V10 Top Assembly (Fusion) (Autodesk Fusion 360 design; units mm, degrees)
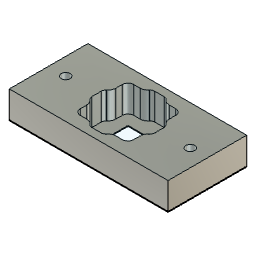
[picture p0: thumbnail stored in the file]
sketch "Sketch1" plane through (0, 0, 0) normal (0, 0, 1) x axis (1, 0, 0)
  line L1 (17.82, 5.59) -> (0, 5.59)
  line L2 (17.82, 8.82) -> (17.82, 0)
  line L3 (9.8201, 1.0463) -> (9.8489, 1.0851)
  line L4 (6.544, 1.41) -> (7.2771, 1.41)
  line L5 (10.5429, 7.41) -> (11.276, 7.41)
  line L6 (12.2349, 3.4711) -> (12.2737, 3.4999)
  line L7 (1.92, 4.41) -> (15.9, 4.41)
  line L8 (0, 3.621) -> (17.82, 3.621)
  line L9 (12.2737, 5.3201) -> (12.2349, 5.3489)
  line L10 (10.09, 0) -> (10.09, 8.82)
  line L11 (11.276, 1.41) -> (10.5429, 1.41)
  line L12 (9.699, 8.82) -> (9.699, 0)
  line L13 (5.5851, 5.3489) -> (5.5463, 5.3201)
  line L14 (12.437, 4.9474) -> (12.437, 3.8726)
  line L15 (17.82, 4.41) -> (15.9, 4.41)
  line L16 (15.9, 8.82) -> (15.9, 4.41)
  line L17 (5.5463, 3.4999) -> (5.5851, 3.4711)
  line L18 (17.82, 0) -> (0, 0)
  line L19 (17.82, 5.199) -> (0, 5.199)
  line L20 (17.82, 3.23) -> (0, 3.23)
  line L21 (0, 0) -> (0, 8.82)
  line L22 (11.91, 2.7771) -> (11.91, 2.044)
  line L23 (1.92, 4.41) -> (0, 4.41)
  line L24 (8.3726, 0.883) -> (9.4474, 0.883)
  line L25 (5.91, 2.7771) -> (5.91, 2.044)
  line L26 (1.92, 0) -> (1.92, 4.41)
  line L27 (15.9, 0) -> (15.9, 4.41)
  line L28 (9.4474, 7.937) -> (8.3726, 7.937)
  line L29 (5.383, 3.8726) -> (5.383, 4.9474)
  line L30 (9.8489, 7.7349) -> (9.8201, 7.7737)
  line L31 (5.91, 6.0429) -> (5.91, 6.776)
  line L32 (7.2771, 7.41) -> (6.544, 7.41)
  line L33 (7.9999, 7.7737) -> (7.9711, 7.7349)
  line L34 (8.121, 0) -> (8.121, 8.82)
  line L35 (1.92, 8.82) -> (1.92, 4.41)
  line L36 (7.9999, 1.0463) -> (7.9711, 1.0851)
  line L37 (11.91, 6.0429) -> (11.91, 6.776)
  line L38 (0, 8.82) -> (17.82, 8.82)
  line L39 (7.73, 8.82) -> (7.73, 0)
  arc A1 centre (12.81, 6.0429) radius 0.9 clockwise from (12.2737, 5.3201) to (11.91, 6.0429)
  arc A2 centre (11.937, 3.8726) radius 0.5 clockwise from (12.437, 3.8726) to (12.2349, 3.4711)
  arc A3 centre (9.4474, 1.383) radius 0.5 clockwise from (9.8489, 1.0851) to (9.4474, 0.883)
  arc A4 centre (11.276, 6.776) radius 0.634 clockwise from (11.276, 7.41) to (11.91, 6.776)
  arc A5 centre (9.4474, 7.437) radius 0.5 clockwise from (9.4474, 7.937) to (9.8489, 7.7349)
  arc A6 centre (11.937, 4.9474) radius 0.5 clockwise from (12.2349, 5.3489) to (12.437, 4.9474)
  arc A7 centre (10.5429, 8.31) radius 0.9 clockwise from (10.5429, 7.41) to (9.8201, 7.7737)
  circle C1 centre (15.9, 4.41) radius 0.5
  circle C2 centre (1.92, 4.41) radius 0.5
  arc A8 centre (8.3726, 7.437) radius 0.5 clockwise from (7.9711, 7.7349) to (8.3726, 7.937)
  arc A9 centre (10.5429, 0.51) radius 0.9 clockwise from (9.8201, 1.0463) to (10.5429, 1.41)
  arc A10 centre (5.01, 6.0429) radius 0.9 clockwise from (5.91, 6.0429) to (5.5463, 5.3201)
  arc A11 centre (5.883, 3.8726) radius 0.5 clockwise from (5.5851, 3.4711) to (5.383, 3.8726)
  arc A12 centre (8.3726, 1.383) radius 0.5 clockwise from (8.3726, 0.883) to (7.9711, 1.0851)
  arc A13 centre (6.544, 2.044) radius 0.634 clockwise from (6.544, 1.41) to (5.91, 2.044)
  arc A14 centre (5.883, 4.9474) radius 0.5 clockwise from (5.383, 4.9474) to (5.5851, 5.3489)
  arc A15 centre (7.2771, 8.31) radius 0.9 clockwise from (7.9999, 7.7737) to (7.2771, 7.41)
  arc A16 centre (5.01, 2.7771) radius 0.9 clockwise from (5.5463, 3.4999) to (5.91, 2.7771)
  arc A17 centre (12.81, 2.7771) radius 0.9 clockwise from (11.91, 2.7771) to (12.2737, 3.4999)
  arc A18 centre (11.276, 2.044) radius 0.634 clockwise from (11.91, 2.044) to (11.276, 1.41)
  arc A19 centre (7.2771, 0.51) radius 0.9 clockwise from (7.2771, 1.41) to (7.9999, 1.0463)
  arc A20 centre (6.544, 6.776) radius 0.634 clockwise from (5.91, 6.776) to (6.544, 7.41)
  point P28 (0, 0)
  point P80 (0, 0)
  point P29 (1.92, 4.41)
  point P34 (1.92, 4.41)
  point P35 (1.92, 8.82)
  point P31 (1.92, 4.41)
  point P30 (1.92, 0)
  point P15 (15.9, 4.41)
  point P39 (15.9, 4.41)
  point P38 (15.9, 8.82)
  point P36 (15.9, 4.41)
  point P37 (15.9, 0)
  point P5 (15.9, 4.41)
  point P6 (17.82, 4.41)
  point P27 (15.9, 4.41)
  point P82 (1.92, 4.41)
  point P33 (0, 4.41)
  point P32 (1.92, 4.41)
  point P98 (0, 5.199)
  point P95 (17.82, 5.199)
  point P89 (17.82, 3.621)
  point P90 (0, 3.621)
  point P41 (0, 3.23)
  point P97 (0, 5.59)
  point P93 (17.82, 5.59)
  point P96 (8.121, 8.82)
  point P92 (8.121, 0)
  point P81 (9.699, 0)
  point P83 (9.699, 8.82)
  point P88 (10.09, 8.82)
  point P84 (10.09, 0)
  point P91 (7.73, 0)
  point P94 (7.73, 8.82)
  point P65 (11.276, 1.41)
  point P20 (11.91, 6.776)
  point P57 (6.544, 7.41)
  point P22 (5.91, 2.044)
  horizontal L18
  vertical L2
  horizontal L38
  vertical L21
  coincident P28 P80
  coincident P29 P34
  coincident P35 L38
  perpendicular L35 L38
  coincident P29 P31
  coincident P30 L18
  perpendicular L18 L26
  coincident P15 P39
  coincident P38 L38
  perpendicular L16 L38
  coincident P15 P36
  coincident P37 L18
  perpendicular L18 L27
  coincident P5 P15
  midpoint P6 L2
  coincident P15 P27
  coincident P29 P82
  perpendicular L7 L26
  midpoint P33 L21
  coincident P29 P32
  perpendicular L23 L26
  coincident P98 L21
  coincident P95 L2
  perpendicular L2 L19
  coincident P89 L2
  coincident P90 L21
  perpendicular L8 L21
  coincident P41 L21
  perpendicular L20 L21
  perpendicular L4 L21
  coincident P97 L21
  coincident P93 L2
  perpendicular L1 L2
  perpendicular L5 L21
  coincident P96 L38
  coincident P92 L18
  perpendicular L18 L34
  coincident P81 L18
  coincident P83 L38
  perpendicular L12 L38
  coincident P88 L38
  coincident P84 L18
  perpendicular L10 L18
  perpendicular L22 L38
  coincident P91 L18
  coincident P94 L38
  perpendicular L38 L39
  perpendicular L18 L31
  perpendicular L18 L29
  perpendicular L14 L38
  perpendicular L2 L28
  perpendicular L21 L24
  tangent L31 A20
  tangent L5 A20
  tangent L5 A4
  tangent A4 L22
  tangent L4 A13
  tangent A13 L31
  tangent L4 A18
  tangent L22 A18
  coincident P65 L4
  tangent L4 A19
  tangent A19 L36
  tangent A12 L36
  tangent L24 A12
  tangent A3 L24
  tangent L3 A3
  tangent L3 A9
  tangent L11 A9
  coincident P20 L22
  tangent L22 A17
  tangent L6 A17
  tangent L6 A2
  tangent A2 L14
  tangent A6 L14
  tangent L9 A6
  tangent A1 L9
  tangent A1 L37
  coincident P57 L5
  tangent A7 L30
  tangent L5 A7
  tangent A5 L28
  tangent A5 L30
  tangent A15 L32
  tangent A15 L33
  tangent A8 L33
  tangent A8 L28
  coincident P22 L31
  tangent L13 A10
  tangent A10 L31
  tangent A14 L29
  tangent L13 A14
  tangent L17 A11
  tangent A11 L29
  tangent L17 A16
  tangent L25 A16
  dimension "d1" distance L2 L21 = 17.82
  dimension "d2" distance L18 L38 = 8.82
  dimension "d3" diameter C2 = 1
  dimension "d4" diameter C1 = 1
  dimension "d5" distance L21 L26 = 1.92
  dimension "d6" distance L2 L27 = 1.92
  dimension "d7" distance L12 L34 = 1.578
  dimension "d8" distance L2 L12 = 8.121
  dimension "d9" distance L10 L39 = 2.36
  dimension "d10" distance L2 L10 = 7.73
  dimension "d11" distance L22 L31 = 6
  dimension "d12" distance L2 L22 = 5.91
  dimension "d13" distance L14 L29 = 7.054
  dimension "d14" distance L2 L14 = 5.383
  dimension "d15" distance L8 L19 = 1.578
  dimension "d16" distance L19 L38 = 3.621
  dimension "d17" distance L1 L20 = 2.36
  dimension "d18" distance L1 L38 = 3.23
  dimension "d19" distance L4 L5 = 6
  dimension "d20" distance L5 L38 = 1.41
  dimension "d21" distance L24 L28 = 7.054
  dimension "d22" distance L28 L38 = 0.883
  dimension "d23" radius A20 = 0.634
  dimension "d24" radius A4 = 0.634
  dimension "d25" radius A13 = 0.634
  dimension "d26" radius A18 = 0.634
  dimension "d27" radius A19 = 0.9
  dimension "d28" radius A12 = 0.5
  dimension "d29" radius A3 = 0.5
  dimension "d30" radius A9 = 0.9
  dimension "d31" radius A17 = 0.9
  dimension "d32" radius A2 = 0.5
  dimension "d33" radius A6 = 0.5
  dimension "d34" radius A1 = 0.9
  dimension "d35" radius A7 = 0.9
  dimension "d36" radius A5 = 0.5
  dimension "d37" radius A15 = 0.9
  dimension "d38" radius A8 = 0.5
  dimension "d39" radius A10 = 0.9
  dimension "d40" radius A14 = 0.5
  dimension "d41" radius A11 = 0.5
  dimension "d42" radius A16 = 0.9
extrude "Extrude1" new body sketch "Sketch1" along normal blind 3 bodies "L1 - ACRYLIC"
sketch "Sketch2" plane through (0, 0, 3) normal (0, 0, 1) x axis (-1, 0, 0)
  line L1 (-7.2771, -7.41) -> (-6.544, -7.41)
  line L2 (-7.9711, -7.7349) -> (-7.9999, -7.7737)
  line L3 (-9.4474, -7.937) -> (-8.3726, -7.937)
  line L4 (-9.8201, -7.7737) -> (-9.8489, -7.7349)
  line L5 (-11.276, -7.41) -> (-10.5429, -7.41)
  line L6 (-11.91, -6.0429) -> (-11.91, -6.776)
  line L7 (-12.2349, -5.3489) -> (-12.2737, -5.3201)
  line L8 (-12.437, -3.8726) -> (-12.437, -4.9474)
  line L9 (-12.2737, -3.4999) -> (-12.2349, -3.4711)
  line L10 (-11.91, -2.044) -> (-11.91, -2.7771)
  line L11 (-10.5429, -1.41) -> (-11.276, -1.41)
  line L12 (-9.8489, -1.0851) -> (-9.8201, -1.0463)
  line L13 (-8.3726, -0.883) -> (-9.4474, -0.883)
  line L14 (-7.9999, -1.0463) -> (-7.9711, -1.0851)
  line L15 (-6.544, -1.41) -> (-7.2771, -1.41)
  line L16 (-5.91, -2.7771) -> (-5.91, -2.044)
  line L17 (-5.5851, -3.4711) -> (-5.5463, -3.4999)
  line L18 (-5.383, -4.9474) -> (-5.383, -3.8726)
  line L19 (-5.5463, -5.3201) -> (-5.5851, -5.3489)
  line L20 (-5.91, -6.776) -> (-5.91, -6.0429)
  line L21 (0, -8.82) -> (-17.82, -8.82)
  line L22 (0, 0) -> (0, -8.82)
  line L23 (-17.82, 0) -> (0, 0)
  line L24 (-17.82, -8.82) -> (-17.82, 0)
  circle C1 centre (-1.92, -4.41) radius 0.5
  arc A1 centre (-7.2771, -8.31) radius 0.9 clockwise from (-7.9999, -7.7737) to (-7.2771, -7.41)
  arc A2 centre (-8.3726, -7.437) radius 0.5 clockwise from (-7.9711, -7.7349) to (-8.3726, -7.937)
  arc A3 centre (-9.4474, -7.437) radius 0.5 clockwise from (-9.4474, -7.937) to (-9.8489, -7.7349)
  arc A4 centre (-10.5429, -8.31) radius 0.9 clockwise from (-10.5429, -7.41) to (-9.8201, -7.7737)
  arc A5 centre (-11.276, -6.776) radius 0.634 clockwise from (-11.276, -7.41) to (-11.91, -6.776)
  arc A6 centre (-12.81, -6.0429) radius 0.9 clockwise from (-12.2737, -5.3201) to (-11.91, -6.0429)
  arc A7 centre (-11.937, -4.9474) radius 0.5 clockwise from (-12.2349, -5.3489) to (-12.437, -4.9474)
  arc A8 centre (-11.937, -3.8726) radius 0.5 clockwise from (-12.437, -3.8726) to (-12.2349, -3.4711)
  arc A9 centre (-12.81, -2.7771) radius 0.9 clockwise from (-11.91, -2.7771) to (-12.2737, -3.4999)
  arc A10 centre (-11.276, -2.044) radius 0.634 clockwise from (-11.91, -2.044) to (-11.276, -1.41)
  arc A11 centre (-10.5429, -0.51) radius 0.9 clockwise from (-9.8201, -1.0463) to (-10.5429, -1.41)
  arc A12 centre (-9.4474, -1.383) radius 0.5 clockwise from (-9.8489, -1.0851) to (-9.4474, -0.883)
  arc A13 centre (-8.3726, -1.383) radius 0.5 clockwise from (-8.3726, -0.883) to (-7.9711, -1.0851)
  arc A14 centre (-7.2771, -0.51) radius 0.9 clockwise from (-7.2771, -1.41) to (-7.9999, -1.0463)
  arc A15 centre (-6.544, -2.044) radius 0.634 clockwise from (-6.544, -1.41) to (-5.91, -2.044)
  arc A16 centre (-5.01, -2.7771) radius 0.9 clockwise from (-5.5463, -3.4999) to (-5.91, -2.7771)
  arc A17 centre (-5.883, -3.8726) radius 0.5 clockwise from (-5.5851, -3.4711) to (-5.383, -3.8726)
  arc A18 centre (-5.883, -4.9474) radius 0.5 clockwise from (-5.383, -4.9474) to (-5.5851, -5.3489)
  arc A19 centre (-5.01, -6.0429) radius 0.9 clockwise from (-5.91, -6.0429) to (-5.5463, -5.3201)
  arc A20 centre (-6.544, -6.776) radius 0.634 clockwise from (-5.91, -6.776) to (-6.544, -7.41)
  circle C2 centre (-15.9, -4.41) radius 0.5
sketch "Sketch3" plane through (0, 0, 0) normal (0, 0, -1) x axis (1, 0, 0)
  line L1 (6.544, -7.41) -> (7.2771, -7.41)
  line L2 (5.91, -6.0429) -> (5.91, -6.776)
  line L3 (5.5851, -5.3489) -> (5.5463, -5.3201)
  line L4 (5.383, -3.8726) -> (5.383, -4.9474)
  line L5 (5.5463, -3.4999) -> (5.5851, -3.4711)
  line L6 (5.91, -2.044) -> (5.91, -2.7771)
  line L7 (7.2771, -1.41) -> (6.544, -1.41)
  line L8 (7.9711, -1.0851) -> (7.9999, -1.0463)
  line L9 (9.4474, -0.883) -> (8.3726, -0.883)
  line L10 (9.8201, -1.0463) -> (9.8489, -1.0851)
  line L11 (11.276, -1.41) -> (10.5429, -1.41)
  line L12 (11.91, -2.7771) -> (11.91, -2.044)
  line L13 (12.2349, -3.4711) -> (12.2737, -3.4999)
  line L14 (12.437, -4.9474) -> (12.437, -3.8726)
  line L15 (12.2737, -5.3201) -> (12.2349, -5.3489)
  line L16 (11.91, -6.776) -> (11.91, -6.0429)
  line L17 (10.5429, -7.41) -> (11.276, -7.41)
  line L18 (9.8489, -7.7349) -> (9.8201, -7.7737)
  line L19 (8.3726, -7.937) -> (9.4474, -7.937)
  line L20 (7.9999, -7.7737) -> (7.9711, -7.7349)
  line L21 (17.82, -8.82) -> (0, -8.82)
  line L22 (17.82, 0) -> (17.82, -8.82)
  line L23 (0, 0) -> (17.82, 0)
  line L24 (0, -8.82) -> (0, 0)
  line L25 (17.82, -8.82) -> (17.82, 0)
  line L26 (17.82, 0) -> (0, 0)
  line L27 (7.21, -2.71) -> (10.61, -2.71)
  line L28 (10.61, -2.71) -> (10.61, -6.11)
  line L29 (10.61, -6.11) -> (7.21, -6.11)
  line L30 (0, 0) -> (0, -8.82)
  line L31 (7.21, -6.11) -> (7.21, -2.71)
  line L32 (15.9, -4.41) -> (1.92, -4.41)
  line L33 (0, -4.41) -> (1.92, -4.41)
  line L34 (17.82, -4.41) -> (15.9, -4.41)
  line L35 (0, -8.82) -> (17.82, -8.82)
  circle C1 centre (1.92, -4.41) radius 0.5
  arc A1 centre (6.544, -6.776) radius 0.634 clockwise from (6.544, -7.41) to (5.91, -6.776)
  arc A2 centre (5.01, -6.0429) radius 0.9 clockwise from (5.5463, -5.3201) to (5.91, -6.0429)
  arc A3 centre (5.883, -4.9474) radius 0.5 clockwise from (5.5851, -5.3489) to (5.383, -4.9474)
  arc A4 centre (5.883, -3.8726) radius 0.5 clockwise from (5.383, -3.8726) to (5.5851, -3.4711)
  arc A5 centre (5.01, -2.7771) radius 0.9 clockwise from (5.91, -2.7771) to (5.5463, -3.4999)
  arc A6 centre (6.544, -2.044) radius 0.634 clockwise from (5.91, -2.044) to (6.544, -1.41)
  arc A7 centre (7.2771, -0.51) radius 0.9 clockwise from (7.9999, -1.0463) to (7.2771, -1.41)
  arc A8 centre (8.3726, -1.383) radius 0.5 clockwise from (7.9711, -1.0851) to (8.3726, -0.883)
  arc A9 centre (9.4474, -1.383) radius 0.5 clockwise from (9.4474, -0.883) to (9.8489, -1.0851)
  arc A10 centre (10.5429, -0.51) radius 0.9 clockwise from (10.5429, -1.41) to (9.8201, -1.0463)
  arc A11 centre (11.276, -2.044) radius 0.634 clockwise from (11.276, -1.41) to (11.91, -2.044)
  arc A12 centre (12.81, -2.7771) radius 0.9 clockwise from (12.2737, -3.4999) to (11.91, -2.7771)
  arc A13 centre (11.937, -3.8726) radius 0.5 clockwise from (12.2349, -3.4711) to (12.437, -3.8726)
  arc A14 centre (11.937, -4.9474) radius 0.5 clockwise from (12.437, -4.9474) to (12.2349, -5.3489)
  arc A15 centre (12.81, -6.0429) radius 0.9 clockwise from (11.91, -6.0429) to (12.2737, -5.3201)
  arc A16 centre (11.276, -6.776) radius 0.634 clockwise from (11.91, -6.776) to (11.276, -7.41)
  arc A17 centre (10.5429, -8.31) radius 0.9 clockwise from (9.8201, -7.7737) to (10.5429, -7.41)
  arc A18 centre (9.4474, -7.437) radius 0.5 clockwise from (9.8489, -7.7349) to (9.4474, -7.937)
  arc A19 centre (8.3726, -7.437) radius 0.5 clockwise from (8.3726, -7.937) to (7.9711, -7.7349)
  arc A20 centre (7.2771, -8.31) radius 0.9 clockwise from (7.2771, -7.41) to (7.9999, -7.7737)
  circle C2 centre (15.9, -4.41) radius 0.5
  circle C3 centre (1.92, -4.41) radius 0.625
  circle C4 centre (15.9, -4.41) radius 0.625
  point P69 (0, 0)
  point P70 (0, 0)
  point P72 (1.92, -4.41)
  point P75 (1.92, -4.41)
  point P68 (15.9, -4.41)
  point P73 (15.9, -4.41)
  point P79 (17.82, -4.41)
  point P76 (1.92, -4.41)
  point P74 (0, -4.41)
  point P71 (7.21, -6.11)
  point P78 (7.21, -2.71)
  coincident P69 P70
  coincident P72 P75
  coincident P68 P73
  parallel L32 L35
  coincident P79 L25
  perpendicular L25 L34
  coincident P72 P76
  coincident P74 L30
  perpendicular L30 L33
  dimension "d45" distance L25 L30 = 17.82
  dimension "d46" distance L26 L35 = 8.82
  dimension "d47" diameter C3 = 1.25
  dimension "d48" diameter C4 = 1.25
  dimension "d49" distance P72 L30 = 1.92
  dimension "d50" distance P68 L25 = 1.92
  dimension "d51" distance L32 L35 = 4.41
  dimension "d52" distance P71 P78 = 3.4
  dimension "d53" distance L28 L31 = 3.4
  dimension "d54" distance L29 L35 = 2.71
  dimension "d55" distance L25 L28 = 7.21
place_component sketch "Sketch3"
extrude "Extrude1" new body sketch "Sketch3" along normal blind 0.0508 bodies "Layer 2"
component_from_bodies "Body->Comp"
sketch "Sketch4" plane through (0, 0, -0.0508) normal (0, 0, -1) x axis (1, 0, 0)
  line L1 (7.21, -2.71) -> (7.21, -6.11)
  line L2 (10.61, -2.71) -> (7.21, -2.71)
  line L3 (10.61, -6.11) -> (10.61, -2.71)
  line L4 (7.21, -6.11) -> (10.61, -6.11)
  line L5 (17.82, 0) -> (17.82, -8.82)
  line L6 (0, 0) -> (17.82, 0)
  line L7 (0, -8.82) -> (0, 0)
  line L8 (17.82, -8.82) -> (0, -8.82)
  line L9 (5.5463, -3.4999) -> (5.5851, -3.4711)
  line L10 (9.8201, -1.0463) -> (9.8489, -1.0851)
  line L11 (9.4474, -0.883) -> (8.3726, -0.883)
  line L12 (11.276, -1.41) -> (10.5429, -1.41)
  line L13 (11.91, -2.7771) -> (11.91, -2.044)
  line L14 (5.91, -2.044) -> (5.91, -2.7771)
  line L15 (12.2349, -3.4711) -> (12.2737, -3.4999)
  line L16 (17.82, -8.82) -> (17.82, 0)
  line L17 (7.21, -2.71) -> (10.61, -2.71)
  line L18 (0, 0) -> (0, -8.82)
  line L19 (10.61, -2.71) -> (10.61, -6.11)
  line L20 (15.9, -4.41) -> (1.92, -4.41)
  line L21 (17.82, 0) -> (0, 0)
  line L22 (10.61, -6.11) -> (7.21, -6.11)
  line L23 (17.82, -8.82) -> (0, -8.82)
  line L24 (0, -8.82) -> (17.82, -8.82)
  line L25 (17.82, -4.41) -> (15.9, -4.41)
  line L26 (8.3726, -7.937) -> (9.4474, -7.937)
  line L27 (0, 0) -> (17.82, 0)
  line L28 (9.8489, -7.7349) -> (9.8201, -7.7737)
  line L29 (10.5429, -7.41) -> (11.276, -7.41)
  line L30 (11.91, -6.776) -> (11.91, -6.0429)
  line L31 (12.2737, -5.3201) -> (12.2349, -5.3489)
  line L32 (12.437, -4.9474) -> (12.437, -3.8726)
  line L33 (0, -8.82) -> (0, 0)
  line L34 (7.9999, -7.7737) -> (7.9711, -7.7349)
  line L35 (5.383, -3.8726) -> (5.383, -4.9474)
  line L36 (5.5851, -5.3489) -> (5.5463, -5.3201)
  line L37 (5.91, -6.0429) -> (5.91, -6.776)
  line L38 (6.544, -7.41) -> (7.2771, -7.41)
  line L39 (17.82, 0) -> (17.82, -8.82)
  line L40 (7.9711, -1.0851) -> (7.9999, -1.0463)
  line L41 (7.2771, -1.41) -> (6.544, -1.41)
  line L42 (0, -4.41) -> (1.92, -4.41)
  line L43 (7.21, -6.11) -> (7.21, -2.71)
  circle C1 centre (15.9, -4.41) radius 0.5
  circle C2 centre (1.92, -4.41) radius 0.5
  arc A1 centre (11.937, -4.9474) radius 0.5 clockwise from (12.437, -4.9474) to (12.2349, -5.3489)
  circle C3 centre (1.92, -4.41) radius 0.625
  arc A2 centre (12.81, -6.0429) radius 0.9 clockwise from (11.91, -6.0429) to (12.2737, -5.3201)
  arc A3 centre (11.276, -6.776) radius 0.634 clockwise from (11.91, -6.776) to (11.276, -7.41)
  arc A4 centre (9.4474, -7.437) radius 0.5 clockwise from (9.8489, -7.7349) to (9.4474, -7.937)
  arc A5 centre (10.5429, -8.31) radius 0.9 clockwise from (9.8201, -7.7737) to (10.5429, -7.41)
  circle C4 centre (15.9, -4.41) radius 0.625
  arc A6 centre (6.544, -6.776) radius 0.634 clockwise from (6.544, -7.41) to (5.91, -6.776)
  circle C5 centre (1.92, -4.41) radius 0.5
  arc A7 centre (5.01, -6.0429) radius 0.9 clockwise from (5.5463, -5.3201) to (5.91, -6.0429)
  arc A8 centre (5.883, -4.9474) radius 0.5 clockwise from (5.5851, -5.3489) to (5.383, -4.9474)
  arc A9 centre (8.3726, -7.437) radius 0.5 clockwise from (8.3726, -7.937) to (7.9711, -7.7349)
  arc A10 centre (7.2771, -8.31) radius 0.9 clockwise from (7.2771, -7.41) to (7.9999, -7.7737)
  circle C6 centre (15.9, -4.41) radius 0.5
  arc A11 centre (5.883, -3.8726) radius 0.5 clockwise from (5.383, -3.8726) to (5.5851, -3.4711)
  arc A12 centre (5.01, -2.7771) radius 0.9 clockwise from (5.91, -2.7771) to (5.5463, -3.4999)
  arc A13 centre (6.544, -2.044) radius 0.634 clockwise from (5.91, -2.044) to (6.544, -1.41)
  arc A14 centre (7.2771, -0.51) radius 0.9 clockwise from (7.9999, -1.0463) to (7.2771, -1.41)
  arc A15 centre (8.3726, -1.383) radius 0.5 clockwise from (7.9711, -1.0851) to (8.3726, -0.883)
  arc A16 centre (9.4474, -1.383) radius 0.5 clockwise from (9.4474, -0.883) to (9.8489, -1.0851)
  arc A17 centre (10.5429, -0.51) radius 0.9 clockwise from (10.5429, -1.41) to (9.8201, -1.0463)
  arc A18 centre (11.276, -2.044) radius 0.634 clockwise from (11.276, -1.41) to (11.91, -2.044)
  arc A19 centre (12.81, -2.7771) radius 0.9 clockwise from (12.2737, -3.4999) to (11.91, -2.7771)
  arc A20 centre (11.937, -3.8726) radius 0.5 clockwise from (12.2349, -3.4711) to (12.437, -3.8726)
  point P67 (0, 0)
  point P68 (0, 0)
  point P62 (1.92, -4.41)
  point P64 (1.92, -4.41)
  point P54 (15.9, -4.41)
  point P66 (15.9, -4.41)
  point P57 (17.82, -4.41)
  point P65 (1.92, -4.41)
  point P39 (0, -4.41)
  point P61 (7.21, -2.71)
  point P70 (7.21, -6.11)
  coincident P67 P68
  coincident P62 P64
  coincident P54 P66
  parallel L20 L24
  coincident P57 L16
  perpendicular L16 L25
  coincident P62 P65
  coincident P39 L18
  perpendicular L18 L42
  dimension "d71" distance L16 L18 = 17.82
  dimension "d72" distance L21 L24 = 8.82
  dimension "d73" diameter C3 = 1.25
  dimension "d74" diameter C4 = 1.25
  dimension "d75" distance P62 L18 = 1.92
  dimension "d76" distance P66 L16 = 1.92
  dimension "d77" distance L20 L24 = 4.41
  dimension "d78" distance P61 P70 = 3.4
  dimension "d79" distance L19 L43 = 3.4
  dimension "d80" distance L22 L24 = 2.71
  dimension "d81" distance L16 L19 = 7.21
place_component sketch "Sketch4"
extrude "Extrude1" new body sketch "Sketch4" profile of L1 L2 L3 L4 L5 L6 L7 L8 A1 L9 L10 L11 L12 L13 L14 L15 L16 C3 L17 A2 A3 A4 A5 L18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 along normal blind 0.0508
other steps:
base_feature "Base Feature" bodies "L1 - ACRYLIC"
create_component "CreateComponent1" sketch "Sketch3"
create_component "CreateComponent3"
remove_body "RemoveBody1"
create_component "CreateComponent4" sketch "Sketch4"
named bodies: "L1 - ACRYLIC", "Layer 2"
